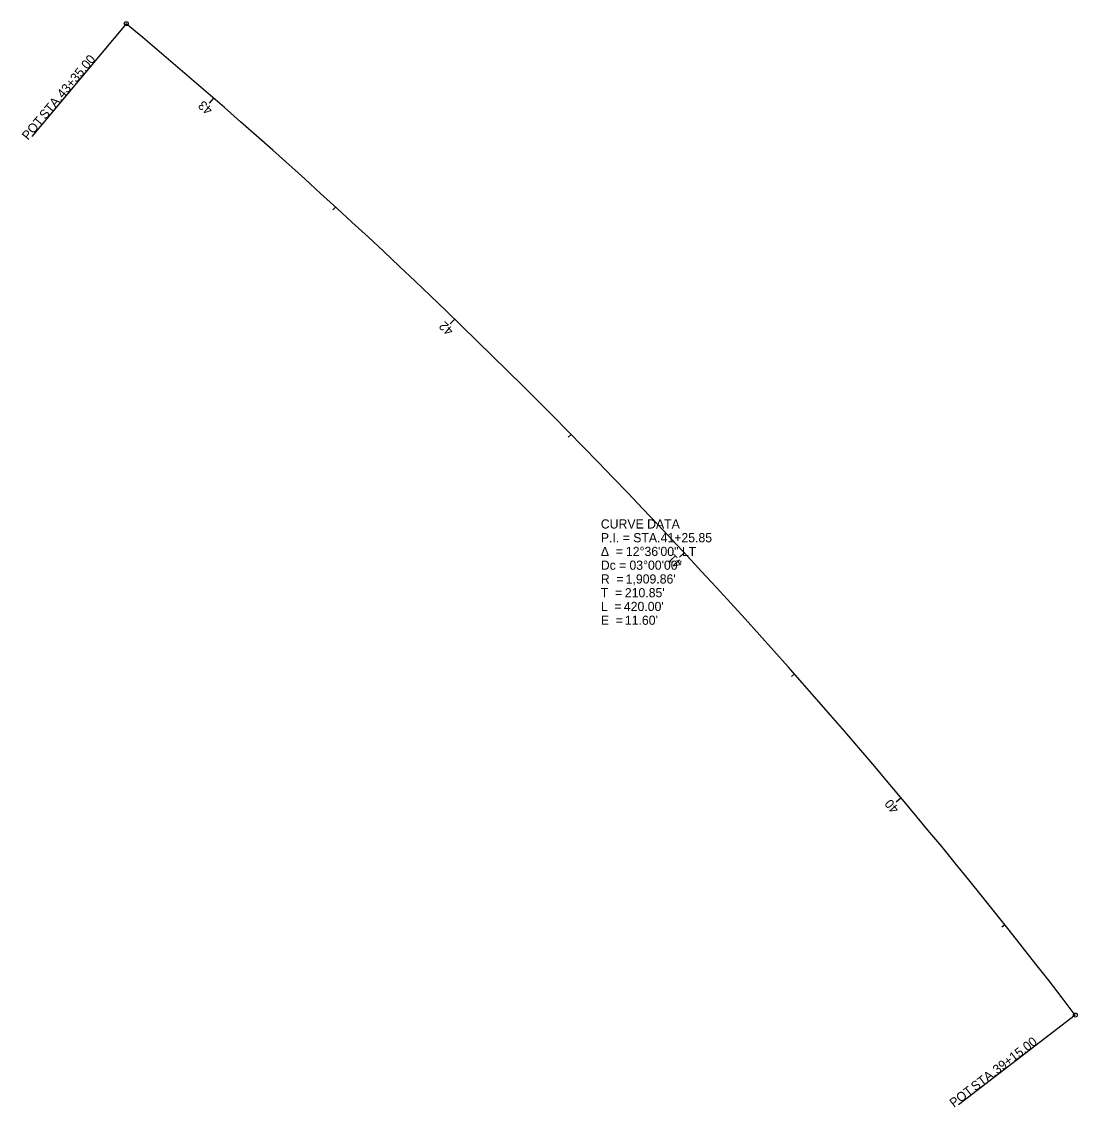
# Model space of a CAD drawing. Extents: x 1700731 to 1701053, y 716398 to 716729.
import ezdxf

# ---------------------------------------------------------------- set-up
doc = ezdxf.new("R2010")
doc.units = 0
for name, color, linetype in [('RW_X_CL_100_Bearings', 7, 'Continuous'), ('RW_X_CL_100_Cardinal_Points', 7, 'Continuous'), ('RW_X_CL_100_Curve_Data', 7, 'Continuous'), ('RW_X_CL_100_Stations', 7, 'Continuous')]:
    doc.layers.add(name, color=color, linetype=linetype)

msp = doc.modelspace()

# ---------------------------------------------------------------- linework, layer by layer
at = {"layer": 'RW_X_CL_100_Bearings'}
for p, q in [((1700762.92, 716728.79), (1700734.03, 716694.29)), ((1701052.81, 716426.04), (1701017.09, 716398.67))]:
    msp.add_line(p, q, dxfattribs=at)
for centre in [(1700762.92, 716728.79), (1701052.81, 716426.04)]:
    msp.add_circle(centre, 0.6, dxfattribs=at)
at = {"layer": 'RW_X_CL_100_Curve_Data'}
for p, q in [((1700789.55, 716706.07), (1700788.24, 716704.56)), ((1700826.86, 716672.78), (1700826.05, 716671.9)), ((1700863.28, 716638.53), (1700861.89, 716637.09)), ((1700898.79, 716603.34), (1700897.93, 716602.49)), ((1700933.37, 716567.22), (1700931.91, 716565.86)), ((1700966.99, 716530.22), (1700966.09, 716529.42)), ((1700999.63, 716492.34), (1700998.1, 716491.06)), ((1701031.27, 716453.63), (1701030.33, 716452.88))]:
    msp.add_line(p, q, dxfattribs=at)
at = {"layer": 'RW_X_CL_100_Stations'}
msp.add_arc((1699536.73, 715264.54), 1909.86, 37.45654, 50.05654, dxfattribs=at)

# ---------------------------------------------------------------- texts
at = {"layer": 'RW_X_CL_100_Bearings'}
for s, rotation, p in [('43+35.00', 50.0565, (1700743.61, 716705.79)), (' STA. ', 50.0565, (1700737.54, 716698.55)), ('POT', 50.0565, (1700732.92, 716693.03)), ('39+15.00', 37.4565, (1701028.95, 716407.81)), (' STA. ', 37.4565, (1701021.44, 716402.06)), ('POT', 37.4565, (1701015.73, 716397.68))]:
    msp.add_text(s, height=2.8, rotation=rotation, dxfattribs=at).set_placement(p)
at = {"layer": 'RW_X_CL_100_Cardinal_Points'}
for s, p in [('CURVE DATA', (1700907.87, 716574.62)), ('P.I. = STA. ', (1700907.87, 716570.42)), ('41+25.85', (1700926.13, 716570.42)), ('Δ  = ', (1700907.87, 716566.22)), ('12°36\'00" LT', (1700915.54, 716566.22)), ('Dc = ', (1700907.87, 716562.02)), ('03°00\'00"', (1700916.61, 716562.02)), ('R  = ', (1700907.87, 716557.82)), ("1,909.86'", (1700915.45, 716557.82)), ('T  = ', (1700907.87, 716553.62)), ("210.85'", (1700915.21, 716553.62)), ('L  = ', (1700907.87, 716549.42)), ("420.00'", (1700914.91, 716549.42)), ('E  = ', (1700907.87, 716545.22)), ("11.60'", (1700915.21, 716545.22))]:
    msp.add_text(s, height=2.8, dxfattribs=at).set_placement(p)
at = {"layer": 'RW_X_CL_100_Curve_Data'}
for s, rotation, p in [('43', 139.0065, (1700789.54, 716702.77)), ('42', 136.0065, (1700863.1, 716635.23)), ('41', 133.0065, (1700932.93, 716564.03)), ('40', 130.0065, (1700999.15, 716489.03))]:
    msp.add_text(s, height=2.8, rotation=rotation, dxfattribs=at).set_placement(p)

doc.saveas('drawing.dxf')
